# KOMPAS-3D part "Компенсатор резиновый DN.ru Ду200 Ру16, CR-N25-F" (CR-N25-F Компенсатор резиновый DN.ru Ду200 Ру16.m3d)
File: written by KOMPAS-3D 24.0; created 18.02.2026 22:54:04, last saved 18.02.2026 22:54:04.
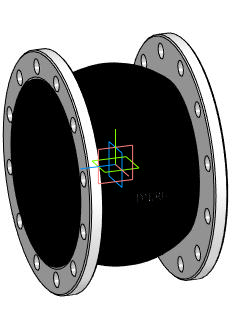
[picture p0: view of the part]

Document properties: Автор: DN.RU; Полное имя файла: D:\PROJECT CAD\DN.RU\...178(1)(ACTUALE). CR-N25-F Компенсатор резиновый DN.ru Ру10-16\DN200_PN16\CR-N25-F Компенсатор резиновый DN.ru Ду200 Ру16.m3d

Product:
- Body: Твердое тело2  | qty 1
    Масса: 46.886983
- Part/product: Компенсатор резиновый DN.ru Ду200 Ру16  | designation CR-N25-F
    Масса: 20
    Раздел спецификации: Прочие изделия
    Комментарий: D140-02400
    Примечание: D140-02400
    additional columns: Типовые

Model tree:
1. Твердое тело2  (labels: Твердое тело2)

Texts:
  CR-N25-F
